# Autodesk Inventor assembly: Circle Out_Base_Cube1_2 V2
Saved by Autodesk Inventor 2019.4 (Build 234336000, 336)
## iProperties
Created: 2020-12
Part Number: Circle Out_Base_Cube1_2 V2
Document SubType Name: Assembly
Designer: Administrator
Title: Circle Out_Base_Cube1_2 V2 v8
Author: Administrator
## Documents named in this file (6)
- c:\worker\convert-fusion-r09\tmp\job-1\10\output\files\e82d7eb4-86c6-4eb0-ab8d-093a554ec036\3123717b-e37c-4948-9e5f-6c321ff58906.iam
- c:\worker\convert-fusion-r09\tmp\job-1\10\output\files\e82d7eb4-86c6-4eb0-ab8d-093a554ec036\Circle Out.ipt
- c:\worker\convert-fusion-r09\tmp\job-1\10\output\files\e82d7eb4-86c6-4eb0-ab8d-093a554ec036\Base.ipt
- c:\worker\convert-fusion-r09\tmp\job-1\10\output\files\e82d7eb4-86c6-4eb0-ab8d-093a554ec036\Cube 1.ipt
- c:\worker\convert-fusion-r09\tmp\job-1\10\output\files\e82d7eb4-86c6-4eb0-ab8d-093a554ec036\Cube 2.ipt
- c:\worker\convert-fusion-r09\tmp\job-1\10\output\files\e82d7eb4-86c6-4eb0-ab8d-093a554ec036\Square In V2.ipt
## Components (5 placed, 5 different names)
1. Circle Out:1
2. Base:1
3. Cube 1:1
4. Cube 2:1
5. Square In V2:1
